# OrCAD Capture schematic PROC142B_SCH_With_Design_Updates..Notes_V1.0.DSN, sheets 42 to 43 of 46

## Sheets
42 42. AUDIO CODEC: size C; title: AUDIO CODEC
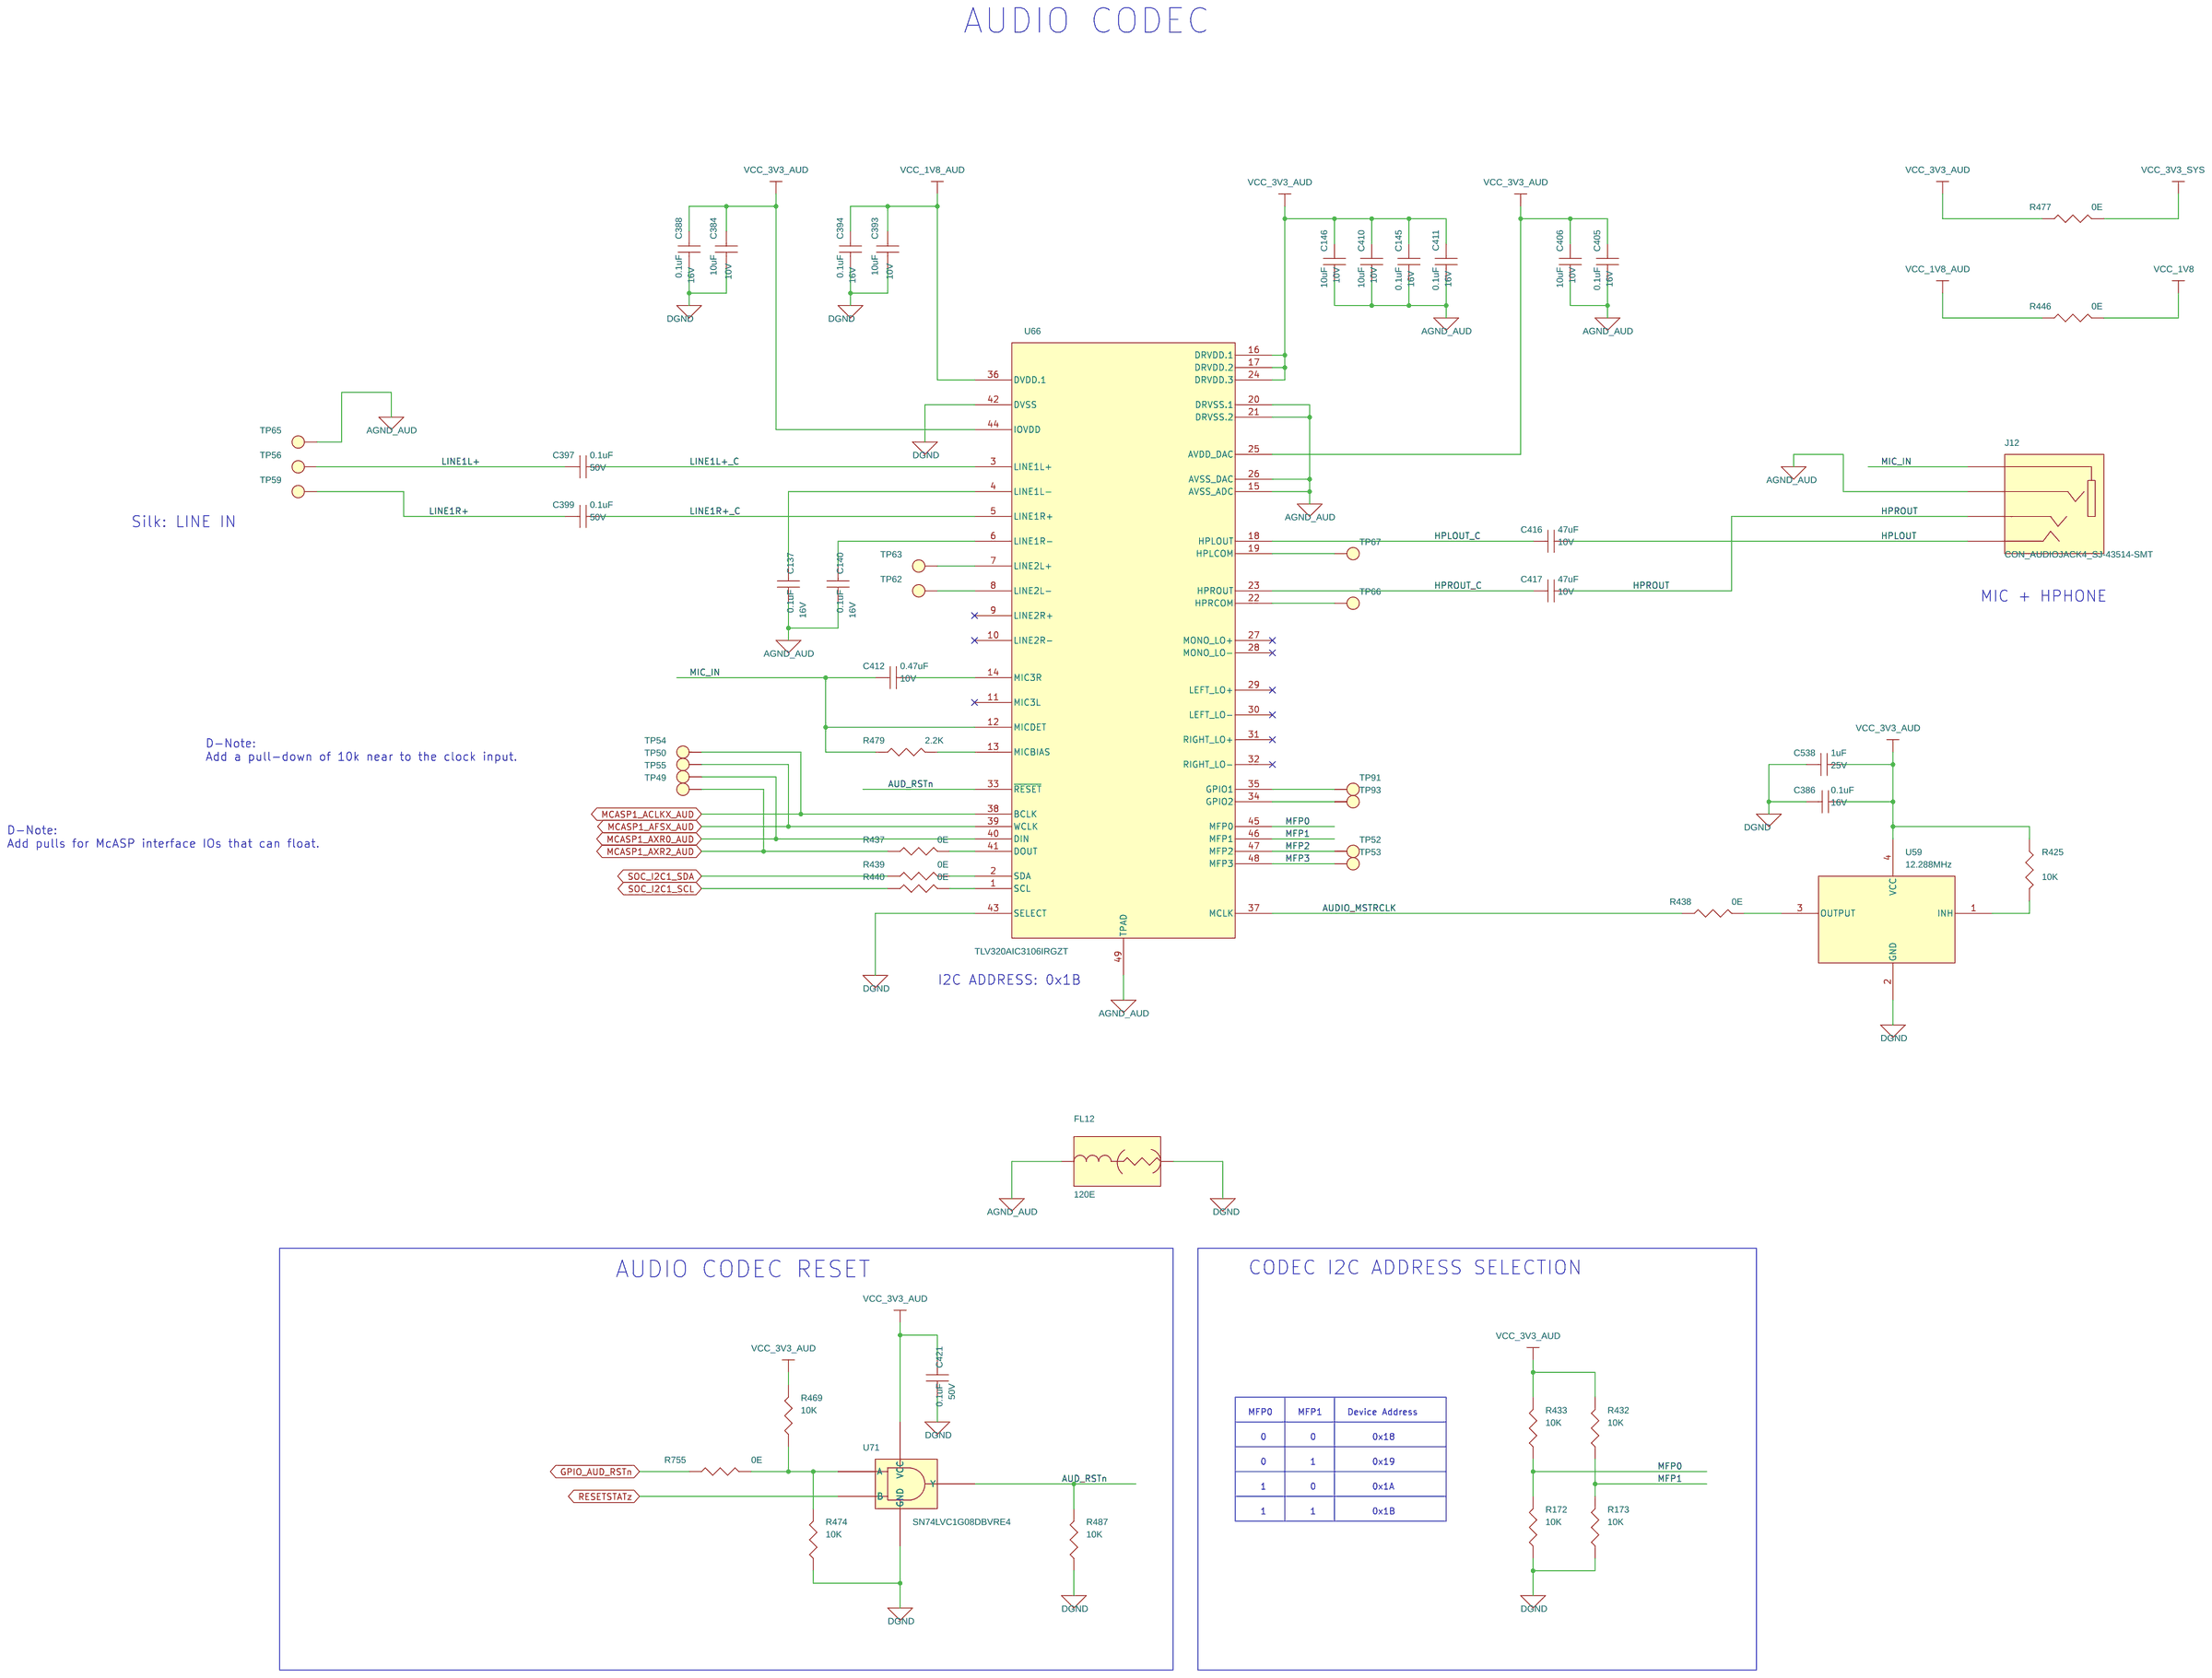
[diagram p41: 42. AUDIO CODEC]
43 43. HDMI INTERFACE: size C; title: SOC DPI INTERFACE, DPI TO HDMI TRANSMITTER INTERFACE
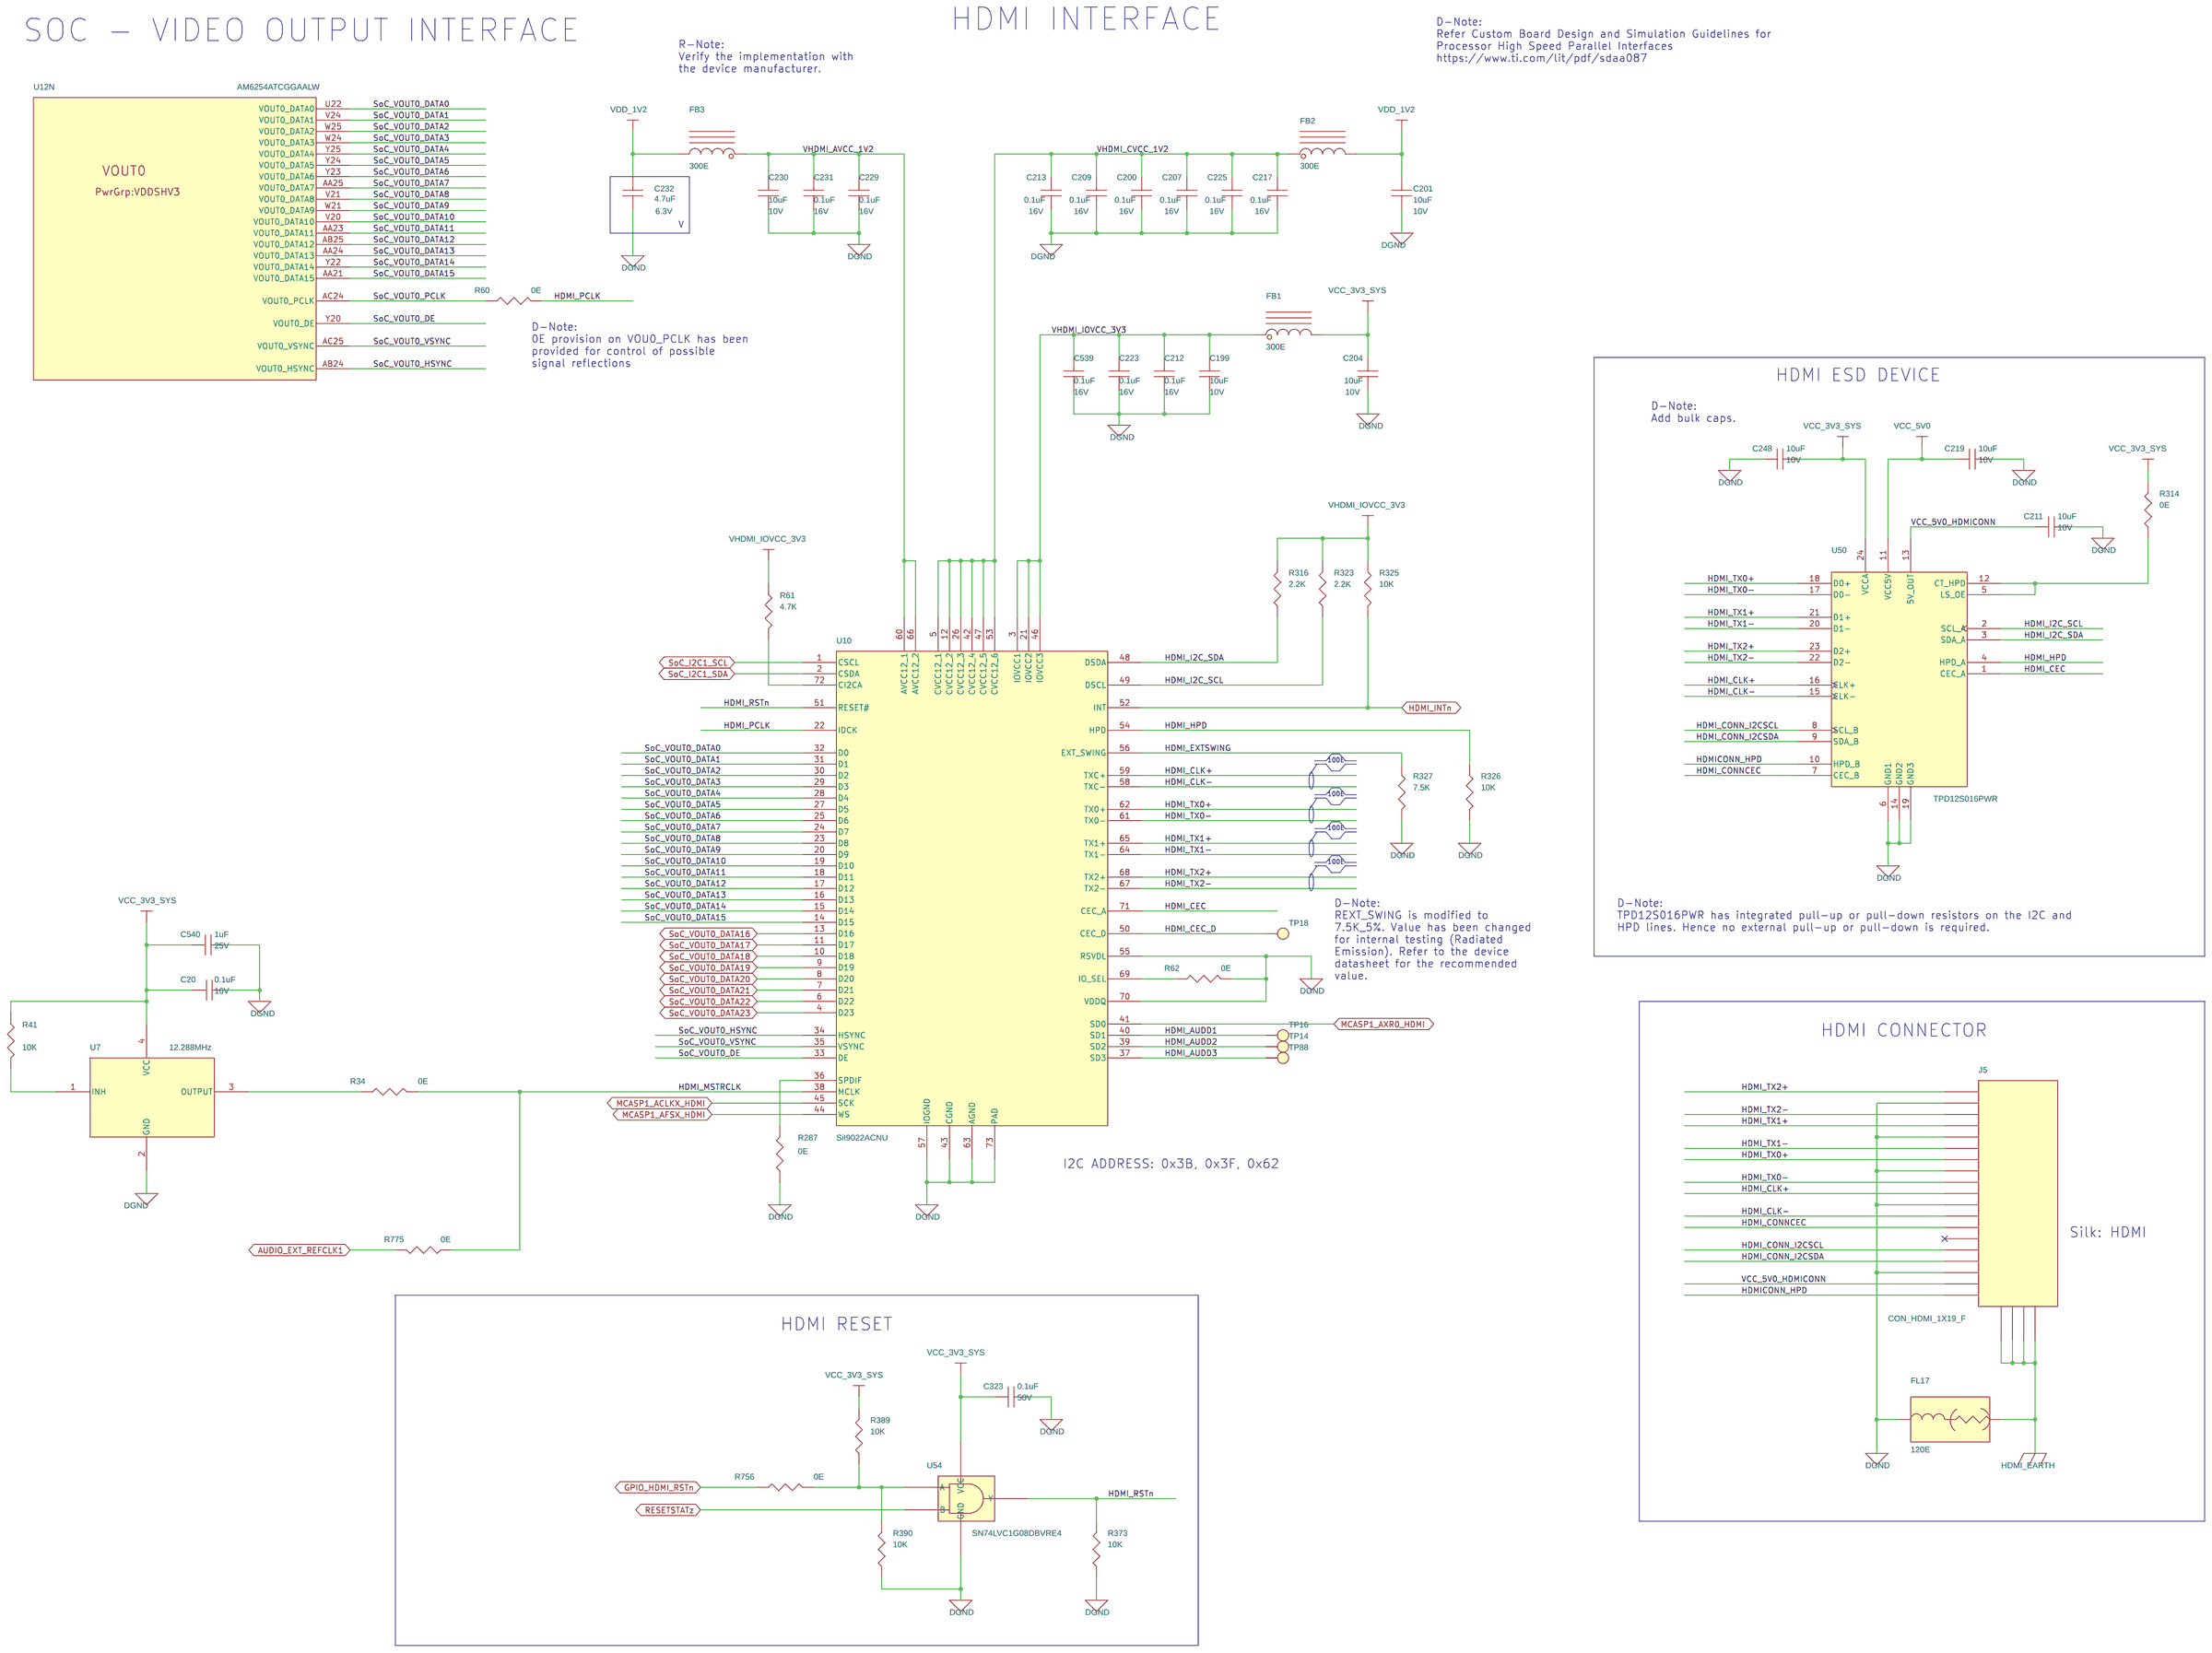
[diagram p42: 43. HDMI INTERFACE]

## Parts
sheet 42. AUDIO CODEC
C137  0.1uF  [CAP0201_0-5]
C140  0.1uF  [CAP0201_0-5]
C145  0.1uF  [CAP0201_0-5]
C146  10uF  [CAP0402_0-75]
C384  10uF  [CAP0402_0-75]
C386  0.1uF  [CAP0201_0-5]
C388  0.1uF  [CAP0201_0-5]
C393  10uF  [CAP0402_0-75]
C394  0.1uF  [CAP0201_0-5]
C397  0.1uF  [CAP0402_0-75]
C399  0.1uF  [CAP0402_0-75]
C405  0.1uF  [CAP0201_0-5]
C406  10uF  [CAP0402_0-75]
C410  10uF  [CAP0402_0-75]
C411  0.1uF  [CAP0201_0-5]
C412  0.47uF  [CAP0402_0-75]
C416  47uF  [CAP1206_2]
C417  47uF  [CAP1206_2]
C421  0.1uF  [CAP0402_0-75]
C538  1uF  [CAP0402_0-75]
FL12  120E  [EMIFIL_BLM15A_0402_0-6]
J12  CON_AUDIOJACK4_SJ-43514-SMT  [CON_AV4_SJ-43514-SMT_S_R_S_5-1]
R172  10K  [RES0201_0-5]
R173  10K  [RES0201_0-5]
R425  10K  [RES0402_0-5]
R432  10K  [RES0201_0-5]
R433  10K  [RES0201_0-5]
R437  0E  [RES0201_0-5]
R438  0E  [RES0201_0-5]
R439  0E  [RES0201_0-5]
R440  0E  [RES0201_0-5]
R446  0E  [RES0201_0-5]
R469  10K  [RES0201_0-5]
R474  10K  [RES0201_0-5]
R477  0E  [RES0201_0-5]
R479  2.2K  [RES0402_0-5]
R487  10K  [RES0201_0-5]
R755  0E  [RES0402_0-5]
TP49  TP20_SMD  [TP20_SMD]
TP50  TP20_SMD  [TP20_SMD]
TP52  TP20_SMD  [TP20_SMD]
TP53  TP20_SMD  [TP20_SMD]
TP54  TP20_SMD  [TP20_SMD]
TP55  TP20_SMD  [TP20_SMD]
TP56  THRU HOLE  [TP_40X65]
TP59  THRU HOLE  [TP_40X65]
TP62  TP20_SMD  [TP20_SMD]
TP63  TP20_SMD  [TP20_SMD]
TP65  THRU HOLE  [TP_40X65]
TP66  TP20_SMD  [TP20_SMD]
TP67  TP20_SMD  [TP20_SMD]
TP91  TP20_SMD  [TP20_SMD]
TP93  TP20_SMD  [TP20_SMD]
U59  12.288MHz  [OSC4_KC2520B_100X80_SMD_0-8]
U66  TLV320AIC3106IRGZT  [VQFN48_19-68_285X285]
U71  SN74LVC1G08DBVRE4  [SOT23-5]
sheet 43. HDMI INTERFACE
C20  0.1uF  [CAP0201_0-5]
C199  10uF  [CAP0402_0-75]
C200  0.1uF  [CAP0201_0-5]
C201  10uF  [CAP0402_0-75]
C204  10uF  [CAP0402_0-75]
C207  0.1uF  [CAP0201_0-5]
C209  0.1uF  [CAP0201_0-5]
C211  10uF  [CAP0402_0-75]
C212  0.1uF  [CAP0201_0-5]
C213  0.1uF  [CAP0201_0-5]
C217  0.1uF  [CAP0201_0-5]
C219  10uF  [CAP0402_0-75]
C223  0.1uF  [CAP0201_0-5]
C225  0.1uF  [CAP0201_0-5]
C229  0.1uF  [CAP0201_0-5]
C230  10uF  [CAP0402_0-75]
C231  0.1uF  [CAP0201_0-5]
C232  4.7uF  [CAP0603_1]
C248  10uF  [CAP0402_0-75]
C323  0.1uF  [CAP0402_0-75]
C539  0.1uF  [CAP0201_0-5]
C540  1uF  [CAP0402_0-75]
FB1  300E  [IND0603]
FB2  300E  [IND0603]
FB3  300E  [IND0603]
FL17  120E  [EMIFIL_BLM15A_0402_0-6]
J5  CON_HDMI_1X19_F  [CON_19X1_10029449-001RLF_S_R_S_6-3]
R34  0E  [RES0402_0-5]
R41  10K  [RES0402_0-5]
R60  0E  [RES0201_0-5]
R61  4.7K  [RES0201_0-5]
R62  0E  [RES0201_0-5]
R287  0E  [RES0201_0-5]
R314  0E  [RES0201_0-5]
R316  2.2K  [RES0402_0-5]
R323  2.2K  [RES0402_0-5]
R325  10K  [RES0201_0-5]
R326  10K  [RES0402_0-5]
R327  7.5K  [RES0402_0-5]
R373  10K  [RES0201_0-5]
R389  10K  [RES0201_0-5]
R390  10K  [RES0201_0-5]
R756  0E  [RES0402_0-5]
R775  0E  [RES0402_0-5]
TP14  TP20_SMD  [TP20_SMD]
TP16  TP20_SMD  [TP20_SMD]
TP18  TP20_SMD  [TP20_SMD]
TP88  TP20_SMD  [TP20_SMD]
U7  12.288MHz  [OSC4_KC2520B_100X80_SMD_0-8]
U10  SiI9022ACNU  [QFN72_19-68_390X390_0-9]
U12  AM6254ATCGGAALW  [BGA425_19-68_510X510_0-7]  (sections A,B,C,D,E,F,G,H,I,J,K,L,M,N,O,P,Q,R)
U50  TPD12S016PWR  [TSSOP24_25-59_315X180_1-2]
U54  SN74LVC1G08DBVRE4  [SOT23-5]

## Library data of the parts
C137 C140 C145 C200 C207 C209 C212 C213 C217 C223 C225 C229 C231 C386 C388 C394 C405 C411 C539 = CAP: CAP CERAMIC 0.1uF 16V 10% X5R 0201; Chkd/date: MANIRAJA/230118; Crtd /date: MANIRAJA/230118; Custom_Duty: 15%; Customs_HS_Code: 85322990; Distributor_name: DIGIKEY; Distributor_part_number: 490-14305-1-ND; Footprint Path: Y:\MIS_DATABASE\Library\ALTIUM_TOOL\PCB_FOOTPRINTS\Altium_Footprint_Lib.PcbLib; Height: 0.33MM; Library Path: Y:\MIS_DATABASE\Library\ALTIUM_TOOL\SCHEMATICS_PARTS\MS_DISCRETE_Library.schlib; Mfr_name: MURATA; Mfr_part_number: GRM033R61C104KE14D; Mistral Part No: 120009030072-R; Package: 0201; Part_type: CAPACITORS\CERAMIC; Project: TI_MAXIE_CPB; RoHS: RoHS; Temperature: -55°C+85°C; Tolerance: 10%; Voltage: 16V; Wattage: NA; Weight: 0.33mg; Datasheet: Y:\MIS_DATABASE\DATASHEETS\CAPACITORS\GRM033R61C104KE14.PDF
C146 C199 C201 C204 C211 C219 C230 C248 C384 C393 C406 C410 = CAP: CAP CERAMIC 10uF 10V 20% X5R 0402; Chkd/date: MANIRAJA/300520; Crtd /date: ALVY/260520; Custom_Duty: 15%; Customs_HS_Code: 85322990; Distributor_name: DIGIKEY; Distributor_part_number: 490-GRM155R61A106ME11DTR-ND; Footprint Path: Y:\MIS_DATABASE\Library\ALTIUM_TOOL\PCB_FOOTPRINTS\Altium_Footprint_Lib.PcbLib; Height: 0.55MM; Library Path: Y:\MIS_DATABASE\Library\ALTIUM_TOOL\SCHEMATICS_PARTS\MS_DISCRETE_Library.schlib; Mfr_name: MURATA; Mfr_part_number: GRM155R61A106ME11D; Mistral Part No: 120013110019-R; Package: 0402; Part_type: CAPACITORS\CERAMIC; Project: QCS610_NANOSOM; RoHS: RoHS; Temperature: -55°C+85°C; Tolerance: 20%; Voltage: 10V; Wattage: NA; Weight: 3.1mg; Datasheet: Y:\MIS_DATABASE\DATASHEETS\CAPACITORS\MURATA-GXX-SER_NOV17.PDF
C397 C399 C421 = CAP: CAP CERAMIC 0.1uF 50V 10% X7R 0402; Chkd/date: MANIRAJA/261020; Crtd /date: ALVY/211020; Custom_Duty: 15%; Customs_HS_Code: 85322990; Distributor_name: DIGIKEY; Distributor_part_number: 490-10700-1-ND; Footprint Path: Y:\MIS_DATABASE\Library\ALTIUM_TOOL\PCB_FOOTPRINTS\Altium_Footprint_Lib.PcbLib; Height: 0.55MM; Library Path: Y:\MIS_DATABASE\Library\ALTIUM_TOOL\SCHEMATICS_PARTS\MS_DISCRETE_Library.schlib; Mfr_name: MURATA; Mfr_part_number: GRM155R71H104KE14D; Mistral Part No: 120011100014-R; Package: 0402; Part_type: CAPACITORS\CERAMIC; Project: J7_CP; RoHS: RoHS; Temperature: -55°C+125°C; Tolerance: 10%; Voltage: 50V; Wattage: NA; Weight: 3.1mg; Datasheet: Y:\MIS_DATABASE\DATASHEETS\CAPACITORS\GRM155R71H104KE14.PDF
C412 = CAP: CAP CERAMIC 0.47uF 10V 10% X7R 0402; Chkd/date: MANIRAJA/310821; Crtd /date: ALVY/310821; Custom_Duty: 15%; Customs_HS_Code: 85322990; Distributor_name: DIGIKEY; Distributor_part_number: 490-14366-1-ND; Footprint Path: Y:\MIS_DATABASE\Library\ALTIUM_TOOL\PCB_FOOTPRINTS\Altium_Footprint_Lib.PcbLib; Height: 0.55MM; Library Path: Y:\MIS_DATABASE\Library\ALTIUM_TOOL\SCHEMATICS_PARTS\MS_DISCRETE_Library.schlib; Mfr_name: MURATA; Mfr_part_number: GRM155R71A474KE01D; Mistral Part No: 120021060019-R; Package: 0402; Part_type: CAPACITORS\CERAMIC; Project: TI_AM335x SK_BRD; RoHS: RoHS; Temperature: -55°C+125°C; Tolerance: 10%; Voltage: 10V; Wattage: NA; Weight: 1.5mg; Datasheet: Y:\MIS_DATABASE\DATASHEETS\CAPACITORS\GRM155R71A474KE01.PDF
C416 C417 = CAP: CAP CERAMIC 47uF 10V 20% X5R 1206; Chkd/date: USMAN/121213; Crtd /date: USMAN/121213; Custom_Duty: 15%; Customs_HS_Code: 85322990; Distributor_name: DIGIKEY; Distributor_part_number: 490-5528-1-ND; Footprint Path: Y:\MIS_DATABASE\Library\ALTIUM_TOOL\PCB_FOOTPRINTS\Altium_Footprint_Lib.PcbLib; Height: 1.80MM; Library Path: Y:\MIS_DATABASE\Library\ALTIUM_TOOL\SCHEMATICS_PARTS\MS_DISCRETE_Library.schlib; Mfr_name: MURATA; Mfr_part_number: GRM31CR61A476ME15L; Mistral Part No: 120013120015-R; Package: 1206; Part_type: CAPACITORS\CERAMIC; Project: DMP; RoHS: RoHS; Temperature: -55°C+85°C; Tolerance: 20%; Voltage: 10V; Wattage: NA; Weight: 40mg; Datasheet: Y:\MIS_DATABASE\DATASHEETS\CAPACITORS\MURATA-GXX-SER_NOV17.PDF
C538 C540 = CAP: CAP CERAMIC 1uF 25V 10% X6S 0402; Chkd/date: MANIRAJA/140518; Crtd /date: ALVY/140518; Custom_Duty: 15%; Customs_HS_Code: 85322990; Distributor_name: DIGIKEY; Distributor_part_number: 490-10014-1-ND; Footprint Path: Y:\MIS_DATABASE\Library\ALTIUM_TOOL\PCB_FOOTPRINTS\Altium_Footprint_Lib.PcbLib; Height: 0.60MM; Library Path: Y:\MIS_DATABASE\Library\ALTIUM_TOOL\SCHEMATICS_PARTS\MS_DISCRETE_Library.schlib; Mfr_name: MURATA; Mfr_part_number: GRM155C81E105KE11D; Mistral Part No: 120018050004-R; Package: 0402; Part_type: CAPACITORS\CERAMIC; Project: TI_SVB_MAXWELL_DUT; RoHS: RoHS; Temperature: -55°C+105°C; Tolerance: 10%; Voltage: 25V; Wattage: NA; Weight: 6mg; Datasheet: Y:\MIS_DATABASE\DATASHEETS\CAPACITORS\GRM155C81E105KE11X.PDF
FL12 FL17 = EMIFILTER_IND: IND FERRITE BEAD CHIP 120E 2A 0402; Chkd/date: NAVEED/241114; Crtd /date: USMAN/170613; Custom_Duty: 24%; Customs_HS_Code: 85369090; Distributor_name: DIGIKEY; Distributor_part_number: 490-9656-1-ND; Footprint Path: Y:\MIS_DATABASE\Library\ALTIUM_TOOL\PCB_FOOTPRINTS\Altium_Footprint_Lib.PcbLib; Height: 0.55MM; Library Path: Y:\MIS_DATABASE\Library\ALTIUM_TOOL\SCHEMATICS_PARTS\MS_FILTER_Library.schlib; Mfr_name: MURATA; Mfr_part_number: BLM15PX121SN1D; Mistral Part No: 130013060022-R; Package: 0402; Part_type: INDUCTOR; Project: GEN_3-8; RoHS: RoHS; Temperature: -55°C+125°C; Tolerance: 25%; Voltage: NA; Wattage: NA; Weight: 1mg; Datasheet: Y:\MIS_DATABASE\DATASHEETS\DISCRETES\INDUCTORS\BLM15-SN1-SER.PDF
J12 = CON_AUDIOJACK4_SJ-43514-SMT: CON AUDIO JACK 4POS FEMALE RT SMD; Chkd/date: MAZHAR/230211; Crtd /date: MUDDU/300610; Custom_Duty: 24%; Customs_HS_Code: 85369090; Distributor_name: DIGIKEY; Distributor_part_number: CP-43514SJCT-ND; Footprint Path: Y:\MIS_DATABASE\Library\ALTIUM_TOOL\PCB_FOOTPRINTS\Altium_Footprint_Lib.PcbLib; Height: 5.10MM; Library Path: Y:\MIS_DATABASE\Library\ALTIUM_TOOL\SCHEMATICS_PARTS\MS_CONNECTOR_Library.schlib; Mfr_name: CUI INC; Mfr_part_number: SJ-43514-SMT-TR; Mistral Part No: 150010060028-R; Package: SMD; Part_type: CONNECTOR\JACK; Project: PB_BUGBASE; RoHS: RoHS; Temperature: -25°C+85°C; Tolerance: NA; Voltage: NA; Wattage: NA; Weight: 1100mg; Datasheet: Y:\MIS_DATABASE\DATASHEETS\CONNECTORS\SJ-4351X-SMT.PDF
R172 R173 R325 R373 R389 R390 R432 R433 R469 R474 R487 = RESISTOR: RES 10K 1/20W 5% 0201; Chkd/date: MANIRAJA/050517; Crtd /date: MANIRAJA/050517; Custom_Duty: 15%; Customs_HS_Code: 85332119; Distributor_name: DIGIKEY; Distributor_part_number: 311-10KNCT-ND; Footprint Path: Y:\MIS_DATABASE\Library\ALTIUM_TOOL\PCB_FOOTPRINTS\Altium_Footprint_Lib.PcbLib; Height: 0.26MM; Library Path: Y:\MIS_DATABASE\Library\ALTIUM_TOOL\SCHEMATICS_PARTS\MS_DISCRETE_Library.schlib; Mfr_name: YAGEO AMERICA; Mfr_part_number: RC0201JR-0710KL; Mistral Part No: 110010070051-R; Package: 0201; Part_type: RESISTORS\FIXED; Project: GOLDEN-I LITE; RoHS: RoHS; Temperature: -55°C+125°C; Tolerance: 5%; Voltage: NA; Wattage: 1/20W; Weight: 0.17mg; Datasheet: Y:\MIS_DATABASE\DATASHEETS\RESISTORS\RCXXXXL-SER_MAR18.PDF
R41 R326 R425 = RESISTOR: RES 10K 1/16W 5% 0402; Chkd/date: MANIRAJA/120219; Crtd /date: MANIRAJA/120219; Custom_Duty: 15%; Customs_HS_Code: 85332119; Distributor_name: DIGIKEY; Distributor_part_number: 541-10KJCT-ND; Footprint Path: Y:\MIS_DATABASE\Library\ALTIUM_TOOL\PCB_FOOTPRINTS\Altium_Footprint_Lib.PcbLib; Height: 0.40MM; Library Path: Y:\MIS_DATABASE\Library\ALTIUM_TOOL\SCHEMATICS_PARTS\MS_DISCRETE_Library.schlib; Mfr_name: VISHAY; Mfr_part_number: CRCW040210K0JNED; Mistral Part No: 110011060021-R; Package: 0402; Part_type: RESISTORS\FIXED; Project: NEXTNAV_ORBIT_MODULE; RoHS: RoHS; Temperature: -55°C+155°C; Tolerance: 5%; Voltage: NA; Wattage: 1/16W; Weight: 0.65mg; Datasheet: Y:\MIS_DATABASE\DATASHEETS\RESISTORS\CRCW0603.PDF
R60 R437 = RESISTOR: RES 0E 1/20W 5% 0201; Chkd/date: NAVEED/301214; Crtd /date: MUDDU/120710; Custom_Duty: 15%; Customs_HS_Code: 85332119; Distributor_name: DIGIKEY; Distributor_part_number: 311-0.0NCT-ND; Footprint Path: Y:\MIS_DATABASE\Library\ALTIUM_TOOL\PCB_FOOTPRINTS\Altium_Footprint_Lib.PcbLib; Height: 0.26MM; Library Path: Y:\MIS_DATABASE\Library\ALTIUM_TOOL\SCHEMATICS_PARTS\MS_DISCRETE_Library.schlib; Mfr_name: YAGEO AMERICA; Mfr_part_number: RC0201JR-070RL; Mistral Part No: 110010070067-R; Package: 0201; Part_type: RESISTORS\FIXED; Project: PB_BUGBASE; RoHS: RoHS; SIGNAL_MODEL: RESISTOR_RES0201_0-5_0E_0E; Temperature: -55°C+125°C; Tolerance: 5%; Voltage: NA; Wattage: 1/20W; Weight: 0.17mg; Datasheet: Y:\MIS_DATABASE\DATASHEETS\RESISTORS\RCXXXXL-SER_MAR18.PDF
R62 R287 R314 R438-R440 R446 R477 = RESISTOR: RES 0E 1/20W 5% 0201; Chkd/date: NAVEED/301214; Crtd /date: MUDDU/120710; Custom_Duty: 15%; Customs_HS_Code: 85332119; Distributor_name: DIGIKEY; Distributor_part_number: 311-0.0NCT-ND; Footprint Path: Y:\MIS_DATABASE\Library\ALTIUM_TOOL\PCB_FOOTPRINTS\Altium_Footprint_Lib.PcbLib; Height: 0.26MM; Library Path: Y:\MIS_DATABASE\Library\ALTIUM_TOOL\SCHEMATICS_PARTS\MS_DISCRETE_Library.schlib; Mfr_name: YAGEO AMERICA; Mfr_part_number: RC0201JR-070RL; Mistral Part No: 110010070067-R; Package: 0201; Part_type: RESISTORS\FIXED; Project: PB_BUGBASE; RoHS: RoHS; Temperature: -55°C+125°C; Tolerance: 5%; Voltage: NA; Wattage: 1/20W; Weight: 0.17mg; Datasheet: Y:\MIS_DATABASE\DATASHEETS\RESISTORS\RCXXXXL-SER_MAR18.PDF
R316 R323 R479 = RESISTOR: RES 2.2K 1/16W 5% 0402; Chkd/date: VASANTHA/061216; Crtd /date: BAVISH/021210; Custom_Duty: 15%; Customs_HS_Code: 85332119; Distributor_name: DIGIKEY; Distributor_part_number: 311-2.2KJRCT-ND; Footprint Path: Y:\MIS_DATABASE\Library\ALTIUM_TOOL\PCB_FOOTPRINTS\Altium_Footprint_Lib.PcbLib; Height: 0.40MM; Library Path: Y:\MIS_DATABASE\Library\ALTIUM_TOOL\SCHEMATICS_PARTS\MS_DISCRETE_Library.schlib; Mfr_name: YAGEO AMERICA; Mfr_part_number: RC0402JR-072K2L; Mistral Part No: 110010120018-R; Package: 0402; Part_type: RESISTORS\FIXED; Project: TE4; RoHS: RoHS; Temperature: -55°C+155°C; Tolerance: 5%; Voltage: NA; Wattage: 1/16W; Weight: 0.65mg; Datasheet: Y:\MIS_DATABASE\DATASHEETS\RESISTORS\RCXXXXL-SER_MAR18.PDF
R34 R755 R756 R775 = RESISTOR: RES 0E 1/16W JUMPER 0402; Chkd/date: VASANTHA/201216; Crtd /date: MUDDU/190810; Custom_Duty: 15%; Customs_HS_Code: 85332119; Distributor_name: DIGIKEY; Distributor_part_number: 541-0.0JCT-ND; Footprint Path: Y:\MIS_DATABASE\Library\ALTIUM_TOOL\PCB_FOOTPRINTS\Altium_Footprint_Lib.PcbLib; Height: 0.40MM; Library Path: Y:\MIS_DATABASE\Library\ALTIUM_TOOL\SCHEMATICS_PARTS\MS_DISCRETE_Library.schlib; Mfr_name: VISHAY; Mfr_part_number: CRCW04020000Z0ED; Mistral Part No: 110010080019-R; Package: 0402; Part_type: RESISTORS\FIXED; Project: PB_BUGBASE; RoHS: RoHS; Temperature: -55°C+155°C; Tolerance: NA; Voltage: NA; Wattage: 1/16W; Weight: 0.65mg; Datasheet: Y:\MIS_DATABASE\DATASHEETS\RESISTORS\CRCW0603.PDF
TP14 TP16 TP18 TP49 TP50 TP52-TP55 TP62 TP63 TP66 TP67 TP88 TP91 TP93 = TESTPOINT: TESTPOINT CIR 20 SMD; Chkd/date: SHREESHAIL/171006; Crtd /date: MAZHAR/171006; Custom_Duty: NA; Customs_HS_Code: NA; Distributor_name: NA; Distributor_part_number: NA; Footprint Path: Y:\MIS_DATABASE\Library\ALTIUM_TOOL\PCB_FOOTPRINTS\Altium_Footprint_Lib.PcbLib; Height: NA; Library Path: Y:\MIS_DATABASE\Library\ALTIUM_TOOL\SCHEMATICS_PARTS\MS_DISCRETE_Library.schlib; MECHANICAL 3D STEP FILE: NA; Mfr_name: LOCAL; Mistral Part No: NA; Package: SMD; Project: BT MODULE_CSRBC04; RoHS: NA; Temperature: NA; Tolerance: NA; Voltage: NA; Wattage: NA; Weight: NA; Datasheet: NA
TP56 TP59 TP65 = TESTPOINT: TESTPOINT 1.0MM DRILL PTH; Chkd/date: MAZHAR/271211; Crtd /date: SHREESHAIL/041005; Distributor_name: NA; Distributor_part_number: NA; Height: NA; Mfr_name: LOCAL; Mistral Part No: 130009030938; Package: THRU-HOLE; Project: HSE; Datasheet: NA
U7 U59 = OSC_KC2016K: OSC 12.288MHz CMOS SMD; Chkd/date: MANIRAJA/061021; Crtd /date: ALVY/061021; Custom_Duty: 24%; Customs_HS_Code: 85437099; Distributor_name: DIGIKEY; Distributor_part_number: 1253-KC2520Z12.2880C1KX00CT-ND; Footprint Path: Y:\MIS_DATABASE\Library\ALTIUM_TOOL\PCB_FOOTPRINTS\Altium_Footprint_Lib.PcbLib; Height: 0.80MM; Library Path: Y:\MIS_DATABASE\Library\ALTIUM_TOOL\SCHEMATICS_PARTS\MS_DISCRETE_Library.schlib; Mfr_name: KYOCERA; Mfr_part_number: KC2520Z12.2880C1KX00; Mistral Part No: 130021100008-R; Package: SMD; Part_type: OSCILLATORS; Project: TI_AM62x SKEVM_BRD; RoHS: RoHS; Temperature: -40°C+85°C; Tolerance: NA; Voltage: NA; Wattage: NA; Weight: NA; Datasheet: Y:\MIS_DATABASE\DATASHEETS\MISC\CRY_OSC\KC-Z-SERPDF
U66 = TLV320AIC3106IRGZT_VQFN48: IC LOW-POWER STEREO AUDIO CODEC VQFN48; Chkd/date: SUHAS/261010; Crtd /date: MUDDU/150610; Custom_Duty: 15%; Customs_HS_Code: 85423100; Distributor_name: DIGIKEY; Distributor_part_number: TLV320AIC3106IRGZT-ND; Height: 1.00MM; Mfr_name: TEXAS INSTRUMENTS; Mistral Part No: 143010060003-R; Package: VQFN48; Part_type: ICS\TELECOM\CODEC; Project: CENTAURUS; RoHS: Sb/ Br FREE; Temperature: -40°C+85°C; Weight: NA; Datasheet: Y:\MIS_DATABASE\DATASHEETS\ICS\TELECOM\TLV320AIC3106IRGZT.PDF
U54 U71 = SN74LVC1G08DBVRE4_SOT23-5: IC SINGLE 2-INPUT POSITIVE AND GATE SOT23-5; Chkd/date: SUHAS/221010; Crtd /date: USMAN/151008; Custom_Duty: 15%; Customs_HS_Code: 85423100; Distributor_name: DIGIKEY; Distributor_part_number: SN74LVC1G08DBVRE4-ND; Height: 1.45MM; Mfr_name: TEXAS INSTRUMENTS; Mistral Part No: 141009060026-R; Part_type: ICS\DIGITAL\GATES; Project: KHAN_MAIN; RoHS: Sb/ Br FREE; Temperature: -40°C+85°C; Datasheet: Y:\MIS_DATABASE\DATASHEETS\ICS\DIGITAL\GATES\SN74LVC1G08.PDF
C20 = CAP: CAP CERAMIC 0.1uF 16V 10% X5R 0201; Alt_Mfr_name: YAGEO AMERICA; Alt_Mfr_part_number: CC0402KRX5R8BB104; Chkd/date: MANIRAJA/230118; Crtd /date: MANIRAJA/230118; Custom_Duty: 15%; Customs_HS_Code: 85322990; Distributor_name: DIGIKEY; Distributor_part_number: 490-14305-1-ND; Footprint Path: Y:\MIS_DATABASE\Library\ALTIUM_TOOL\PCB_FOOTPRINTS\Altium_Footprint_Lib.PcbLib; Height: 0.33MM; Library Path: Y:\MIS_DATABASE\Library\ALTIUM_TOOL\SCHEMATICS_PARTS\MS_DISCRETE_Library.schlib; Mfr_name: MURATA; Mfr_part_number: GRM033R61C104KE14D; Mistral Part No: 120009030072-R; Package: 0201; Part_type: CAPACITORS\CERAMIC; Project: TI_MAXIE_CPB; RoHS: RoHS; Temperature: -55°C+85°C; Tolerance: 10%; Voltage: 16V; Wattage: NA; Weight: 0.33mg; Datasheet: Y:\MIS_DATABASE\DATASHEETS\CAPACITORS\GRM033R61C104KE14.PDF
C232 = CAP: CAP CERAMIC 4.7uF 6.3V 10% X5R AUTO 0603; Chkd/date: JEBRAN/290116; Crtd /date: JEBRAN/290116; Custom_Duty: 15%; Customs_HS_Code: 85369090; Distributor_name: DIGIKEY; Distributor_part_number: 490-12307-1-ND; Footprint Path: Y:\MIS_DATABASE\Library\ALTIUM_TOOL\PCB_FOOTPRINTS\Altium_Footprint_Lib.PcbLib; Height: 0.90MM; Library Path: Y:\MIS_DATABASE\Library\ALTIUM_TOOL\SCHEMATICS_PARTS\MS_DISCRETE_Library.schlib; Mfr_name: MURATA; Mfr_part_number: GRT188R60J475KE01D; Mistral Part No: 120016010019-R; Package: 0603; Part_type: CAPACITORS\CERAMIC; Project: USHUS-2; RoHS: RoHS; Temperature: -55°C+85°C; Tolerance: 10%; Voltage: 6.3V; Wattage: NA; Weight: 2mg; Datasheet: Y:\MIS_DATABASE\DATASHEETS\CAPACITORS\GRT188R60J475KE01D.PDF
C323 = CAP: CAP CERAMIC 0.1uF 50V 10% X7R 0402; Alt_Mfr_name: YAGEO AMERICA; Alt_Mfr_part_number: CC0402KRX5R8BB104; Chkd/date: MANIRAJA/261020; Crtd /date: ALVY/211020; Custom_Duty: 15%; Customs_HS_Code: 85322990; Distributor_name: DIGIKEY; Distributor_part_number: 490-10700-1-ND; Footprint Path: Y:\MIS_DATABASE\Library\ALTIUM_TOOL\PCB_FOOTPRINTS\Altium_Footprint_Lib.PcbLib; Height: 0.55MM; Library Path: Y:\MIS_DATABASE\Library\ALTIUM_TOOL\SCHEMATICS_PARTS\MS_DISCRETE_Library.schlib; Mfr_name: MURATA; Mfr_part_number: GRM155R71H104KE14D; Mistral Part No: 120011100014-R; Package: 0402; Part_type: CAPACITORS\CERAMIC; Project: J7_CP; RoHS: RoHS; Temperature: -55°C+125°C; Tolerance: 10%; Voltage: 50V; Wattage: NA; Weight: 3.1mg; Datasheet: Y:\MIS_DATABASE\DATASHEETS\CAPACITORS\GRM155R71H104KE14.PDF
FB1-FB3 = INDUCTOR_FERRITE: IND FERRITE CHIP 300E 500mA 0603; Alternate_mfr_name_A: TDK CORPORATION; Alternate_mfr_part_number_A: MMZ1608R301ATA00; Chkd/date: VASANTHA/190614; Crtd /date: NAVEED/160614; Custom_Duty: 24%; Customs_HS_Code: 85437099; Distributor_name: DIGIKEY; Distributor_name_A: DIGIKEY; Distributor_part_number: 445-2171-1-ND; Distributor_part_number_A: 445-2171-1-ND; Height: 0.75MM; Mfr_name: TDK CORPORATION; Mfr_part_number: MMZ1608R301A; Mistral Part No: 130014060028-R; Package: 0603; Part_type: INDUCTOR; Project: AEGIS_POM; RoHS: RoHS; Temperature: -55°C+125°C; Tolerance: NA; Voltage: NA; Wattage: NA; Weight: NA; Datasheet: Y:\MIS_DATABASE\DATASHEETS\DISCRETES\INDUCTORS\MMZSER.PDF
J5 = CON_HDMI_19X1: CON HDMI-A TYPE 1X19 0.50MM PITCH FEMALE RT SMD; Chkd/date: VASANTHA/060117; Crtd /date: MUDDU/060510; Custom_Duty: 24%; Customs_HS_Code: 85369090; Distributor_name: DIGIKEY; Distributor_part_number: 609-1010-1-ND; Footprint Path: Y:\MIS_DATABASE\Library\ALTIUM_TOOL\PCB_FOOTPRINTS\Altium_Footprint_Lib.PcbLib; Height: 6.30MM; Library Path: Y:\MIS_DATABASE\Library\ALTIUM_TOOL\SCHEMATICS_PARTS\MS_CONNECTOR_Library.schlib; Mfr_name: FCI; Mfr_part_number: 10029449-001RLF; Mistral Part No: 150010050001-R; Package: SMD; Part_type: CONNECTOR\HDMI; Project: SHIVA; RoHS: RoHS; Temperature: -20°C+85°C; Tolerance: NA; Voltage: NA; Wattage: NA; Weight: 2700mg; Datasheet: Y:\MIS_DATABASE\DATASHEETS\CONNECTORS\10029449-001RLF.PDF
R61 = RESISTOR: RES 4.7K 1/20W 5% 0201; Chkd/date: MANIRAJA/200921; Crtd /date: ALVY/200921; Custom_Duty: 15%; Customs_HS_Code: 85332119; Distributor_name: DIGIKEY; Distributor_part_number: 311-4.7KNCT-ND; Footprint Path: Y:\MIS_DATABASE\Library\ALTIUM_TOOL\PCB_FOOTPRINTS\Altium_Footprint_Lib.PcbLib; Height: 0.26MM; Library Path: Y:\MIS_DATABASE\Library\ALTIUM_TOOL\SCHEMATICS_PARTS\MS_DISCRETE_Library.schlib; Mfr_name: YAGEO AMERICA; Mfr_part_number: RC0201JR-074K7L; Mistral Part No: 110021090007-R; Package: 0201; Part_type: RESISTORS\FIXED; Project: TI_AM62x SKEVM_BRD; RoHS: RoHS; Temperature: -55°C+125°C; Tolerance: 5%; Voltage: NA; Wattage: 1/20W; Weight: 0.17mg; Datasheet: Y:\MIS_DATABASE\DATASHEETS\RESISTORS\RCXXXXL-SER_MAR18.PDF
R327 = RESISTOR: RES 7.5K 1/16W 5% 0402; Chkd/date: MAZHAR/280108; Crtd /date: USMAN/280108; Custom_Duty: 15%; Customs_HS_Code: 85332119; Distributor_name: DIGIKEY; Distributor_part_number: 541-7.5KJCT-ND; Footprint Path: Y:\MIS_DATABASE\Library\ALTIUM_TOOL\PCB_FOOTPRINTS\Altium_Footprint_Lib.PcbLib; Height: 0.40MM; Library Path: Y:\MIS_DATABASE\Library\ALTIUM_TOOL\SCHEMATICS_PARTS\MS_DISCRETE_Library.schlib; Mfr_name: VISHAY; Mfr_part_number: CRCW04027K50JNED; Mistral Part No: 110009031092-R; Package: 0402; Part_type: RESISTORS\FIXED; Project: TELEMETRY ENCODER; RoHS: RoHS; Temperature: -55°C+155°C; Tolerance: 5%; Voltage: NA; Wattage: 1/16W; Weight: 0.65mg; Datasheet: Y:\MIS_DATABASE\DATASHEETS\RESISTORS\CRCW0603.PDF
U10 = SII9022ACNU_QFN72: IC HDMI TRANSMITTER QFN72; Chkd/date: MANIRAJA/270818; Crtd /date: MUDDU/310510; Custom_Duty: 15%; Customs_HS_Code: 85423100; Distributor_name: NA; Distributor_part_number: NA; Footprint Path: Y:\MIS_DATABASE\Library\ALTIUM_TOOL\PCB_FOOTPRINTS\Altium_Footprint_Lib.PcbLib; Height: 0.90MM; Library Path: Y:\MIS_DATABASE\Library\ALTIUM_TOOL\SCHEMATICS_PARTS\MS_COMBINATIONAL_Library.schlib; Library Ref: SiI9022ACNU_QFN72; Mfr_name: SILICON IMAGE; Mistral Part No: 141010060001; Package: QFN72; Part_type: ICS\DIGITAL\PERIPHERAL; Project: CENTAURUS; RoHS: NA; Temperature: -20°C+85°C; Tolerance: NA; Voltage: NA; Wattage: NA; Weight: NA; Datasheet: Y:\MIS_DATABASE\DATASHEETS\ICS\DIGITAL\PERIPHERAL\SiI9022.PDF
U12 = AM62-EVM_BGA425: IC AM62 SoC MICROPROCESSOR BGA425; Chkd/date: ALVY/110621; Crtd /date: MANIRAJA/110621; Custom_Duty: 15%; Customs_HS_Code: 85423100; Distributor_name: NA; Distributor_part_number: NA; Footprint Path: Y:\MIS_DATABASE\Library\ALTIUM_TOOL\PCB_FOOTPRINTS\Altium_Footprint_Lib.PcbLib; Height: 0.65MM; Library Path: Y:\MIS_DATABASE\Library\ALTIUM_TOOL\SCHEMATICS_PARTS\MS_MICROPROCESSOR_Library.schlib; Mfr_name: TEXAS INSTRUMENTS; Mistral Part No: 141221060001; Package: BGA425; Part_type: ICS\DIGITAL\MICROPROCESSOR; Project: AM62_EVM_BRD; RoHS: NA; Temperature: NA; Tolerance: NA; Voltage: NA; Wattage: NA; Weight: NA; Datasheet: Y:\MIS_DATABASE\DATASHEETS\ICS\DIGITAL\MICROCONTROLLER\AM62-SoC_SVB.PDF
U50 = TPD12S016PW_TSSOP24: IC HDMI COMPANION CHIP WITH I2C LEVEL SHIFTING,12-CH ESD TSSOP24; Chkd/date: MANIRAJA/110917; Crtd /date: BAVISH/180811; Custom_Duty: 15%; Customs_HS_Code: 85423100; Distributor_name: DIGIKEY; Distributor_part_number: 296-29690-1-ND; Height: 1.20MM; Mfr_name: TEXAS INSTRUMENTS; Mistral Part No: 141011080021-R; Package: TSSOP24; Part_type: ICS\INTERFACE; Project: DM385EVM_BASE-BOARD; RoHS: RoHS; Temperature: -40°C+85°C; Tolerance: NA; Voltage: NA; Wattage: NA; Weight: 212mg; Datasheet: Y:\MIS_DATABASE\DATASHEETS\ICS\INTERFACE\TPD12S016.PDF

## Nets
AGND_AUD: C137.2 C140.2 C145.2 C146.2 C405.2 C406.2 C410.2 C411.2 FL12.1 J12.4 TP65.1(TP) U66.15(AVSS_ADC) U66.20(DRVSS.1) U66.21(DRVSS.2) U66.26(AVSS_DAC) U66.49(TPAD)
DGND: C20.1 C199.2 C200.2 C201.2 C204.2 C207.2 C209.2 C211.2 C212.2 C213.2 C217.2 C219.2 C223.2 C225.2 C229.2 C230.2 C231.2 C232.2 C248.1 C323.2 C384.2 C386.2 C388.2 C393.2 C394.2 C421.2 C538.1 C539.2 C540.2 FL12.2 FL17.1 J5.2 J5.5 J5.8 J5.11 J5.17 R62.2 R172.2 R173.2 R287.1 R326.2 R327.2 R373.1 R390.1 R474.1 R487.1 U7.2(GND) U10.43(CGND) U10.55(RSVDL) U10.57(IOGND) U10.63(AGND) U10.70(VDDQ) U10.73(PAD) U50.6(GND1) U50.14(GND2) U50.19(GND3) U54.3(GND) U59.2(GND) U66.42(DVSS) U66.43(SELECT) U71.3(GND) ; also on sheet 1 3 12 13 14 15 16 17 18 19 20 21 22 23 24 25 26 27 28 29 30 31 32 33 34 35 36 37 38 39 40 41 44 45
VCC_1V8: R446.2 ; also on sheet 14 15 20 21 23 27 36 39 41 44
VCC_1V8_AUD: C393.1 C394.1 R446.1 U66.36(DVDD.1)
VCC_3V3_AUD: C145.1 C146.1 C384.1 C386.1 C388.1 C405.1 C406.1 C410.1 C411.1 C421.1 C538.2 R425.1 R432.1 R433.1 R469.2 R477.1 U59.4(VCC) U66.16(DRVDD.1) U66.17(DRVDD.2) U66.24(DRVDD.3) U66.25(AVDD_DAC) U66.44(IOVDD) U71.5(VCC)
VCC_3V3_SYS: C20.2 C204.1 C248.2 C323.1 C540.1 FB1.2 R41.1 R314.2 R389.2 R477.2 U7.4(VCC) U50.24(VCCA) U54.5(VCC) ; also on sheet 3 12 14 15 16 20 21 22 24 25 26 27 28 29 31 32 33 34 35 36 37 38 39 40 41 44 45
VCC_5V0: C219.1 U50.11(VCC5V) ; also on sheet 12 13 17 35 38
VCC_5V0_HDMICONN: C211.1 J5.18 U50.13(5V_OUT)
VDD_1V2: C201.1 C232.1 FB2.2 FB3.2 ; also on sheet 15
AUD_RSTn: R487.2 U66.33(~{RESET}) U71.4(Y)
AUDIO_EXT_REFCLK1: R775.2 ; also on sheet 35
AUDIO_MSTRCLK: R438.1 U66.37(MCLK)
GPIO_AUD_RSTn: R755.2 ; also on sheet 41
GPIO_HDMI_RSTn: R756.2 ; also on sheet 41
HDMI_AUDD1: TP16.1(TP) U10.40(SD1)
HDMI_AUDD2: TP14.1(TP) U10.39(SD2)
HDMI_AUDD3: TP88.1(TP) U10.37(SD3)
HDMI_CEC: U10.71(CEC_A) U50.1(CEC_A)
HDMI_CEC_D: TP18.1(TP) U10.50(CEC_D)
HDMI_CLK+: J5.10 U10.59(TXC+) U50.16(CLK+)
HDMI_CLK-: J5.12 U10.58(TXC-) U50.15(CLK-)
HDMI_CONN_I2CSCL: J5.15 U50.8(SCL_B)
HDMI_CONN_I2CSDA: J5.16 U50.9(SDA_B)
HDMI_CONNCEC: J5.13 U50.7(CEC_B)
HDMI_EARTH: FL17.2 J5.20 J5.21 J5.22 J5.23
HDMI_EXTSWING: R327.1 U10.56(EXT_SWING)
HDMI_HPD: R326.1 U10.54(HPD) U50.4(HPD_A)
HDMI_I2C_SCL: R323.1 U10.49(DSCL) U50.2(SCL_A)
HDMI_I2C_SDA: R316.1 U10.48(DSDA) U50.3(SDA_A)
HDMI_INTn: R325.2 U10.52(INT) ; also on sheet 41
HDMI_MSTRCLK: R34.1 R775.1 U10.38(MCLK)
HDMI_PCLK: R60.2 U10.22(IDCK)
HDMI_RSTn: R373.2 U10.51(RESET#) U54.4(Y)
HDMI_TX0+: J5.7 U10.62(TX0+) U50.18(D0+)
HDMI_TX0-: J5.9 U10.61(TX0-) U50.17(D0-)
HDMI_TX1+: J5.4 U10.65(TX1+) U50.21(D1+)
HDMI_TX1-: J5.6 U10.64(TX1-) U50.20(D1-)
HDMI_TX2+: J5.1 U10.68(TX2+) U50.23(D2+)
HDMI_TX2-: J5.3 U10.67(TX2-) U50.22(D2-)
HDMICONN_HPD: J5.19 U50.10(HPD_B)
HPLOUT: C416.2 J12.2
HPLOUT_C: C416.1 U66.18(HPLOUT)
HPROUT: C417.2 J12.3
HPROUT_C: C417.1 U66.23(HPROUT)
LINE1L+: C397.1 TP56.1(TP)
LINE1L+_C: C397.2 U66.3(LINE1L+)
LINE1R+: C399.1 TP59.1(TP)
LINE1R+_C: C399.2 U66.5(LINE1R+)
MCASP1_ACLKX_AUD: TP54.1(TP) U66.38(BCLK) ; also on sheet 41
MCASP1_ACLKX_HDMI: U10.45(SCK) ; also on sheet 41
MCASP1_AFSX_AUD: TP50.1(TP) U66.39(WCLK) ; also on sheet 41
MCASP1_AFSX_HDMI: U10.44(WS) ; also on sheet 41
MCASP1_AXR0_AUD: TP55.1(TP) U66.40(DIN) ; also on sheet 41
MCASP1_AXR0_HDMI: U10.41(SD0) ; also on sheet 41
MCASP1_AXR2_AUD: R437.1 TP49.1(TP) ; also on sheet 41
MFP0: R172.1 R433.2 U66.45(MFP0)
MFP1: R173.1 R432.2 U66.46(MFP1)
MFP2: TP52.1(TP) U66.47(MFP2)
MFP3: TP53.1(TP) U66.48(MFP3)
MIC_IN: C412.1 J12.1 R479.1 U66.12(MICDET)
RESETSTATz: U54.2(B) U71.2(B) ; also on sheet 15 21 22 23 25 26 29 34 35 39 41 44
SOC_I2C1_SCL: R440.1 U10.1(CSCL) ; also on sheet 3 16 24 28 41 44
SOC_I2C1_SDA: R439.1 U10.2(CSDA) ; also on sheet 3 16 24 28 41 44
SoC_VOUT0_DATA0: U10.32(D0) U12.U22(VOUT0_DATA0)
SoC_VOUT0_DATA1: U10.31(D1) U12.V24(VOUT0_DATA1)
SoC_VOUT0_DATA2: U10.30(D2) U12.W25(VOUT0_DATA2)
SoC_VOUT0_DATA3: U10.29(D3) U12.W24(VOUT0_DATA3)
SoC_VOUT0_DATA4: U10.28(D4) U12.Y25(VOUT0_DATA4)
SoC_VOUT0_DATA5: U10.27(D5) U12.Y24(VOUT0_DATA5)
SoC_VOUT0_DATA6: U10.25(D6) U12.Y23(VOUT0_DATA6)
SoC_VOUT0_DATA7: U10.24(D7) U12.AA25(VOUT0_DATA7)
SoC_VOUT0_DATA8: U10.23(D8) U12.V21(VOUT0_DATA8)
SoC_VOUT0_DATA9: U10.20(D9) U12.W21(VOUT0_DATA9)
SoC_VOUT0_DATA10: U10.19(D10) U12.V20(VOUT0_DATA10)
SoC_VOUT0_DATA11: U10.18(D11) U12.AA23(VOUT0_DATA11)
SoC_VOUT0_DATA12: U10.17(D12) U12.AB25(VOUT0_DATA12)
SoC_VOUT0_DATA13: U10.16(D13) U12.AA24(VOUT0_DATA13)
SoC_VOUT0_DATA14: U10.15(D14) U12.Y22(VOUT0_DATA14)
SoC_VOUT0_DATA15: U10.14(D15) U12.AA21(VOUT0_DATA15)
SoC_VOUT0_DATA16: U10.13(D16) ; also on sheet 34
SoC_VOUT0_DATA17: U10.11(D17) ; also on sheet 34
SoC_VOUT0_DATA18: U10.10(D18) ; also on sheet 34
SoC_VOUT0_DATA19: U10.9(D19) ; also on sheet 34
SoC_VOUT0_DATA20: U10.8(D20) ; also on sheet 34
SoC_VOUT0_DATA21: U10.7(D21) ; also on sheet 34
SoC_VOUT0_DATA22: U10.6(D22) ; also on sheet 34
SoC_VOUT0_DATA23: U10.4(D23) ; also on sheet 34
SoC_VOUT0_DE: U10.33(DE) U12.Y20(VOUT0_DE)
SoC_VOUT0_HSYNC: U10.34(HSYNC) U12.AB24(VOUT0_HSYNC)
SoC_VOUT0_PCLK: R60.1 U12.AC24(VOUT0_PCLK)
SoC_VOUT0_VSYNC: U10.35(VSYNC) U12.AC25(VOUT0_VSYNC)
VHDMI_AVCC_1V2: C229.1 C230.1 C231.1 FB3.1 U10.60(AVCC12_1) U10.66(AVCC12_2)
VHDMI_CVCC_1V2: C200.1 C207.1 C209.1 C213.1 C217.1 C225.1 FB2.1 U10.5(CVCC12_1) U10.12(CVCC12_2) U10.26(CVCC12_3) U10.42(CVCC12_4) U10.47(CVCC12_5) U10.53(CVCC12_6)
VHDMI_IOVCC_3V3: C199.1 C212.1 C223.1 C539.1 FB1.1 R61.1 R316.2 R323.2 R325.1 U10.3(IOVCC1) U10.21(IOVCC2) U10.46(IOVCC3)
N16927060: R61.2 U10.72(CI2CA)
N16927228: R62.1 U10.69(IO_SEL)
N16927289: R287.2 U10.36(SPDIF)
N16927312: R389.1 R390.2 R756.1 U54.1(A)
N16929396: R469.1 R474.2 R755.1 U71.1(A)
N16929458: TP63.1(TP) U66.7(LINE2L+)
N16929460: TP62.1(TP) U66.8(LINE2L-)
N16929474: R437.2 U66.41(DOUT)
N16929699: C137.1 U66.4(LINE1L-)
N16929703: C140.1 U66.6(LINE1R-)
N16929744: TP67.1(TP) U66.19(HPLCOM)
N16929747: TP66.1(TP) U66.22(HPRCOM)
N16929749: TP91.1(TP) U66.35(GPIO1)
N16929751: TP93.1(TP) U66.34(GPIO2)
N17285208: R314.1 U50.5(LS_OE) U50.12(CT_HPD)
N17498937: R439.2 U66.2(SDA)
N17498940: R440.2 U66.1(SCL)
N18736007: C412.2 U66.14(MIC3R)
N18736028: R479.2 U66.13(MICBIAS)
N20174887: R425.2 U59.1(INH)
N20174906: R438.2 U59.3(OUTPUT)
N20175126: R34.2 U7.3(OUTPUT)
N20175146: R41.2 U7.1(INH)

Not connected (* = marked no-connect by the designer): J5 14*; U66 9(LINE2R+)* 10(LINE2R-)* 11(MIC3L)* 27(MONO_LO+)* 28(MONO_LO-)* 29(LEFT_LO+)* 30(LEFT_LO-)* 31(RIGHT_LO+)* 32(RIGHT_LO-)*

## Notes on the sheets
sheet 42
- AUDIO CODEC
- Silk: LINE IN
- MIC + HPHONE
- D-Note:
  Add a pull-down of 10k near to the clock input.
- D-Note:
  Add pulls for McASP interface IOs that can float.
- I2C ADDRESS: 0x1B
- AUDIO CODEC RESET
- CODEC I2C ADDRESS SELECTION
- MFP0
- MFP1
- Device Address
- 0
- 0
- 0x18
- 0
- 1
- 0x19
- 1
- 0
- 0x1A
- 1
- 1
- 0x1B
sheet 43
- HDMI INTERFACE
- SOC - VIDEO OUTPUT INTERFACE
- D-Note:
  Refer Custom Board Design and Simulation Guidelines for
  Processor High Speed Parallel Interfaces
  https://www.ti.com/lit/pdf/sdaa087
- R-Note:
  Verify the implementation with
  the device manufacturer.
- V
- D-Note:
  0E provision on VOU0_PCLK has been
  provided for control of possible
  signal reflections
- HDMI ESD DEVICE
- D-Note:
  Add bulk caps.
- 100E
- 100E
- 100E
- 100E
- D-Note:
  REXT_SWING is modified to
  7.5K_5%. Value has been changed
  for internal testing (Radiated
  Emission). Refer to the device
  datasheet for the recommended
  value.
- D-Note:
  TPD12S016PWR has integrated pull-up or pull-down resistors on the I2C and
  HPD lines. Hence no external pull-up or pull-down is required.
- HDMI CONNECTOR
- I2C ADDRESS: 0x3B, 0x3F, 0x62
- Silk: HDMI
- HDMI RESET
